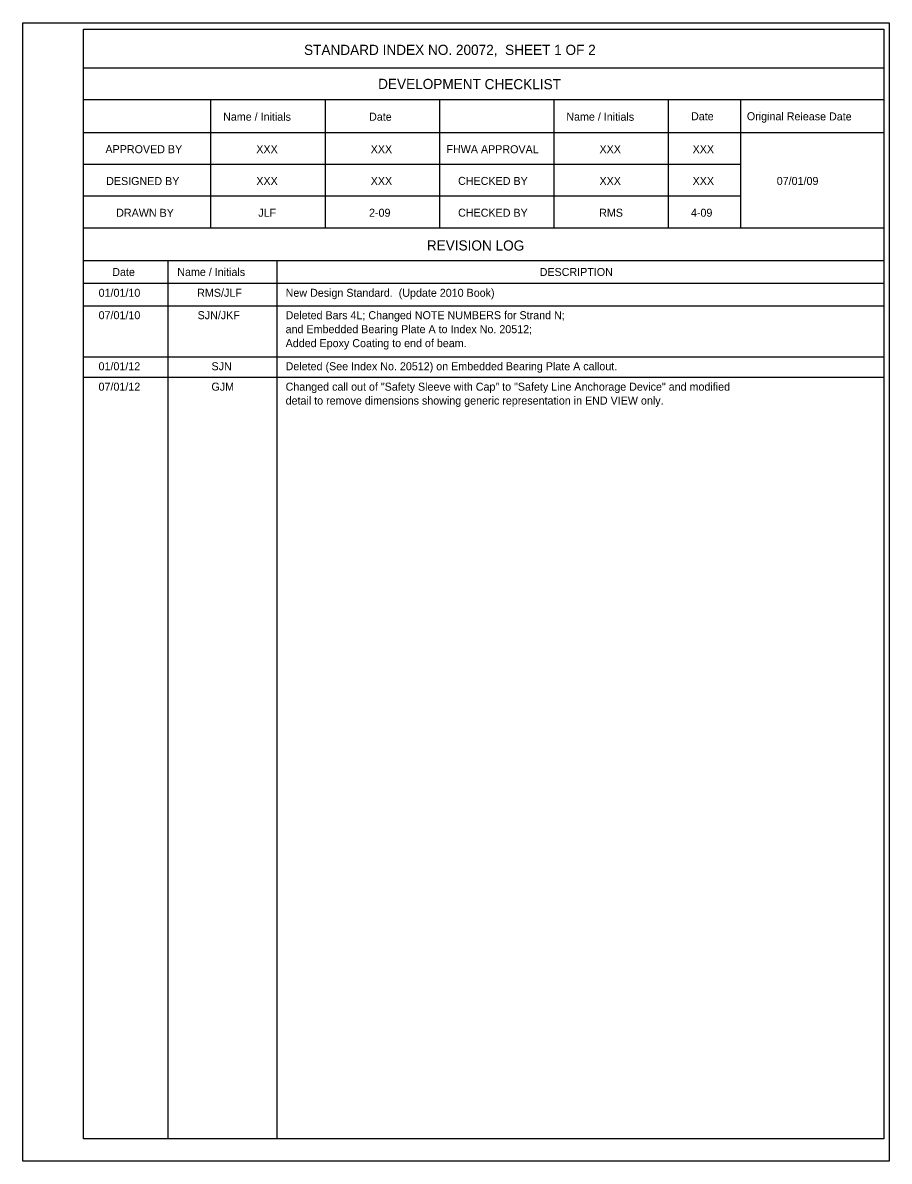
# Model space of a CAD drawing. Extents: x 4.6 to 40.7, y -0.9 to 17.4.
# Drawn here: x 29.79 to 40.7, y 2.25 to 16.59 of the extents above; entities that cross this region are included whole.
import ezdxf

# ---------------------------------------------------------------- set-up
doc = ezdxf.new("R2010")
doc.units = 0
for name, color, linetype in [('Border', 7, 'Continuous'), ('Dimension', 7, 'Continuous'), ('PlotBorder_dp', 7, 'Continuous'), ('TextStructures', 7, 'Continuous')]:
    doc.layers.add(name, color=color, linetype=linetype)

msp = doc.modelspace()

# ---------------------------------------------------------------- linework, layer by layer
at = {"layer": 'Border'}
for p, q in [((40.633, 16.015), (30.559, 16.015)), ((40.633, 15.615), (30.559, 15.615)), ((32.159, 15.615), (32.159, 14.002)), ((33.599, 15.615), (33.599, 14.002)), ((35.039, 15.615), (35.039, 14.002)), ((36.479, 15.615), (36.479, 14.002)), ((37.919, 15.615), (37.919, 14.002)), ((38.827, 15.615), (38.827, 14.002)), ((40.633, 15.202), (30.559, 15.202)), ((38.827, 14.802), (30.559, 14.802)), ((38.827, 14.402), (30.559, 14.402)), ((40.633, 14.002), (30.559, 14.002)), ((40.633, 13.588), (30.559, 13.588)), ((31.62, 13.588), (31.62, 2.534)), ((32.991, 13.588), (32.991, 2.534)), ((40.633, 13.306), (30.559, 13.306))]:
    msp.add_line(p, q, dxfattribs=at)
msp.add_lwpolyline([(30.56, 16.506), (40.633, 16.506), (40.633, 2.534), (30.56, 2.534)], close=True, dxfattribs=at)
at = {"layer": 'Dimension'}
for p, q in [((30.559, 13.024), (40.633, 13.024)), ((30.559, 12.381), (40.633, 12.381)), ((30.559, 12.124), (40.633, 12.124))]:
    msp.add_line(p, q, dxfattribs=at)
at = {"layer": 'PlotBorder_dp'}
msp.add_line((29.794, 2.254), (29.794, 2.254), dxfattribs=at)
msp.add_lwpolyline([(29.794, 16.587), (40.701, 16.587), (40.701, 2.254), (29.794, 2.254)], close=True, dxfattribs=at)

# ---------------------------------------------------------------- texts
at = {"layer": 'TextStructures'}
for s, height, p in [('STANDARD INDEX NO. 20072,  SHEET 1 OF 2', 0.128, (33.335, 16.182)), ('XXX', 0.1008, (32.734, 14.945)), ('XXX', 0.1008, (34.174, 14.945)), ('XXX', 0.1008, (37.054, 14.945)), ('XXX', 0.1008, (38.226, 14.945)), ('XXX', 0.1008, (32.734, 14.545)), ('XXX', 0.1008, (34.174, 14.545)), ('XXX', 0.1008, (37.054, 14.545)), ('XXX', 0.1008, (38.226, 14.545)), ('07/01/09', 0.1008, (39.285, 14.545)), ('JLF', 0.1008, (32.759, 14.145)), ('2-09', 0.1008, (34.153, 14.145)), ('RMS', 0.1008, (37.05, 14.145)), ('4-09', 0.1008, (38.205, 14.145)), ('DESCRIPTION', 0.1008, (36.301, 13.399)), ('01/01/10', 0.1008, (30.749, 13.137)), ('RMS/JLF', 0.1008, (31.99, 13.137)), ('New Design Standard.  (Update 2010 Book)', 0.1008, (33.103, 13.137)), ('07/01/10', 0.1008, (30.749, 12.855)), ('SJN/JKF', 0.1008, (31.995, 12.855)), ('Deleted Bars 4L; Changed NOTE NUMBERS for Strand N;', 0.1008, (33.103, 12.855)), ('and Embedded Bearing Plate A to Index No. 20512;', 0.1008, (33.103, 12.679)), ('Added Epoxy Coating to end of beam.', 0.1008, (33.103, 12.503)), ('01/01/12', 0.1008, (30.748, 12.212)), ('SJN', 0.1008, (32.17, 12.212)), ('Deleted (See Index No. 20512) on Embedded Bearing Plate A callout.', 0.1008, (33.103, 12.212)), ('07/01/12', 0.1008, (30.748, 11.955)), ('GJM', 0.1008, (32.169, 11.955)), ('Changed call out of "Safety Sleeve with Cap" to "Safety Line Anchorage Device" and modified', 0.1008, (33.103, 11.955)), ('detail to remove dimensions showing generic representation in END VIEW only.', 0.1008, (33.103, 11.78))]:
    msp.add_text(s, height=height, dxfattribs=at).set_placement(p)
for s, height, p in [('DEVELOPMENT CHECKLIST', 0.128, (34.267, 15.754)), ('Name / Initials', 0.1008, (32.316, 15.355)), ('Date', 0.1008, (34.153, 15.354)), ('Name / Initials', 0.1008, (36.636, 15.355)), ('Date', 0.1008, (38.206, 15.36)), ('Original Release Date', 0.1008, (38.909, 15.36)), ('APPROVED BY', 0.1008, (30.835, 14.946)), ('FHWA APPROVAL', 0.1008, (35.127, 14.946)), ('DESIGNED BY', 0.1008, (30.844, 14.545)), ('CHECKED BY', 0.1008, (35.274, 14.546)), ('DRAWN BY', 0.1008, (30.97, 14.145)), ('CHECKED BY', 0.1008, (35.274, 14.146)), ('REVISION LOG', 0.128, (34.88, 13.721)), ('Date', 0.1008, (30.921, 13.399)), ('Name / Initials', 0.1008, (31.739, 13.4))]:
    msp.add_text(s, height=height, rotation=359.8756, dxfattribs=at).set_placement(p)

doc.saveas('drawing.dxf')
